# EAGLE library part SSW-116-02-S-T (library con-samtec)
THROUGH-HOLE .025" SQ POST SOCKET Source: Samtec SSW.pdf
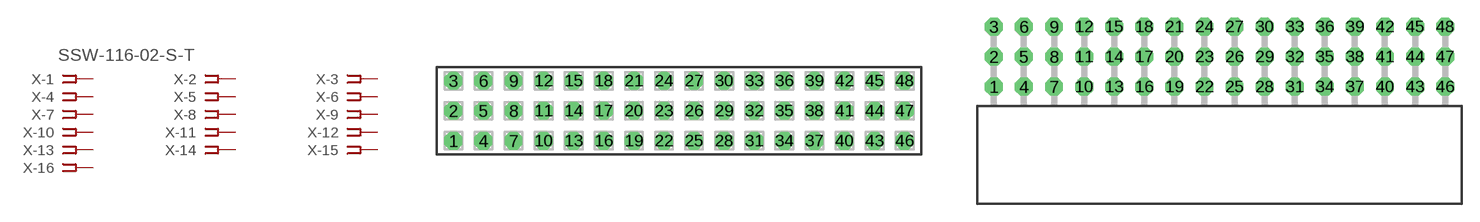
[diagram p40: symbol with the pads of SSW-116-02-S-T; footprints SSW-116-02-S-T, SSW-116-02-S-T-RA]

Designator prefix X; gates -1=FPINV -2=FPIN -3=FPIN -4=FPIN -5=FPIN -6=FPIN -7=FPIN -8=FPIN -9=FPIN -10=FPIN -11=FPIN -12=FPIN -13=FPIN -14=FPIN -15=FPIN -16=FPIN -17=FPIN -18=FPIN -19=FPIN -20=FPIN -21=FPIN -22=FPIN -23=FPIN -24=FPIN -25=FPIN -26=FPIN -27=FPIN -28=FPIN -29=FPIN -30=FPIN -31=FPIN -32=FPIN -33=FPIN -34=FPIN -35=FPIN -36=FPIN -37=FPIN -38=FPIN -39=FPIN -40=FPIN -41=FPIN -42=FPIN -43=FPIN -44=FPIN -45=FPIN -46=FPIN -47=FPIN -48=FPIN

## SSW-116-02-S-T (MPN: SSW-116-02-S-T; OC_FARNELL: unknown; OC_NEWARK: 82P7261)  [SSW-116-02-S-T]
1  -1:1  pas
2  -2:1  pas
3  -3:1  pas
4  -4:1  pas
5  -5:1  pas
6  -6:1  pas
7  -7:1  pas
8  -8:1  pas
9  -9:1  pas
10  -10:1  pas
11  -11:1  pas
12  -12:1  pas
13  -13:1  pas
14  -14:1  pas
15  -15:1  pas
16  -16:1  pas
17  -17:1  pas
18  -18:1  pas
19  -19:1  pas
20  -20:1  pas
21  -21:1  pas
22  -22:1  pas
23  -23:1  pas
24  -24:1  pas
25  -25:1  pas
26  -26:1  pas
27  -27:1  pas
28  -28:1  pas
29  -29:1  pas
30  -30:1  pas
31  -31:1  pas
32  -32:1  pas
33  -33:1  pas
34  -34:1  pas
35  -35:1  pas
36  -36:1  pas
37  -37:1  pas
38  -38:1  pas
39  -39:1  pas
40  -40:1  pas
41  -41:1  pas
42  -42:1  pas
43  -43:1  pas
44  -44:1  pas
45  -45:1  pas
46  -46:1  pas
47  -47:1  pas
48  -48:1  pas

## SSW-116-02-S-TRA (MPN: SSW-116-02-S-T-RA; OC_FARNELL: unknown; OC_NEWARK: 82P7262)  [SSW-116-02-S-T-RA]
Pads as for SSW-116-02-S-T

## Footprint SSW-116-02-S-T (pad centres in mm)
THROUGH-HOLE .025" SQ POST SOCKET Source: Samtec SSW.pdf
drill 1 pad 1.5 octagon: 1 -19.05,-2.54; 2 -19.05,0; 3 -19.05,2.54; 4 -16.51,-2.54; 5 -16.51,0; 6 -16.51,2.54; 7 -13.97,-2.54; 8 -13.97,0; 9 -13.97,2.54; 10 -11.43,-2.54; 11 -11.43,0; 12 -11.43,2.54; 13 -8.89,-2.54; 14 -8.89,0; 15 -8.89,2.54; 16 -6.35,-2.54; 17 -6.35,0; 18 -6.35,2.54; 19 -3.81,-2.54; 20 -3.81,0; 21 -3.81,2.54; 22 -1.27,-2.54; 23 -1.27,0; 24 -1.27,2.54; 25 1.27,-2.54; 26 1.27,0; 27 1.27,2.54; 28 3.81,-2.54; 29 3.81,0; 30 3.81,2.54; 31 6.35,-2.54; 32 6.35,0; 33 6.35,2.54; 34 8.89,-2.54; 35 8.89,0; 36 8.89,2.54; 37 11.43,-2.54; 38 11.43,0; 39 11.43,2.54; 40 13.97,-2.54; 41 13.97,0; 42 13.97,2.54; 43 16.51,-2.54; 44 16.51,0; 45 16.51,2.54; 46 19.05,-2.54; 47 19.05,0; 48 19.05,2.54

## Footprint SSW-116-02-S-T-RA (pad centres in mm)
THROUGH-HOLE .025" SQ POST SOCKET Source: Samtec SSW.pdf
drill 1 pad 1.5 octagon: 1 -19.05,1.524; 2 -19.05,4.064; 3 -19.05,6.604; 4 -16.51,1.524; 5 -16.51,4.064; 6 -16.51,6.604; 7 -13.97,1.524; 8 -13.97,4.064; 9 -13.97,6.604; 10 -11.43,1.524; 11 -11.43,4.064; 12 -11.43,6.604; 13 -8.89,1.524; 14 -8.89,4.064; 15 -8.89,6.604; 16 -6.35,1.524; 17 -6.35,4.064; 18 -6.35,6.604; 19 -3.81,1.524; 20 -3.81,4.064; 21 -3.81,6.604; 22 -1.27,1.524; 23 -1.27,4.064; 24 -1.27,6.604; 25 1.27,1.524; 26 1.27,4.064; 27 1.27,6.604; 28 3.81,1.524; 29 3.81,4.064; 30 3.81,6.604; 31 6.35,1.524; 32 6.35,4.064; 33 6.35,6.604; 34 8.89,1.524; 35 8.89,4.064; 36 8.89,6.604; 37 11.43,1.524; 38 11.43,4.064; 39 11.43,6.604; 40 13.97,1.524; 41 13.97,4.064; 42 13.97,6.604; 43 16.51,1.524; 44 16.51,4.064; 45 16.51,6.604; 46 19.05,1.524; 47 19.05,4.064; 48 19.05,6.604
